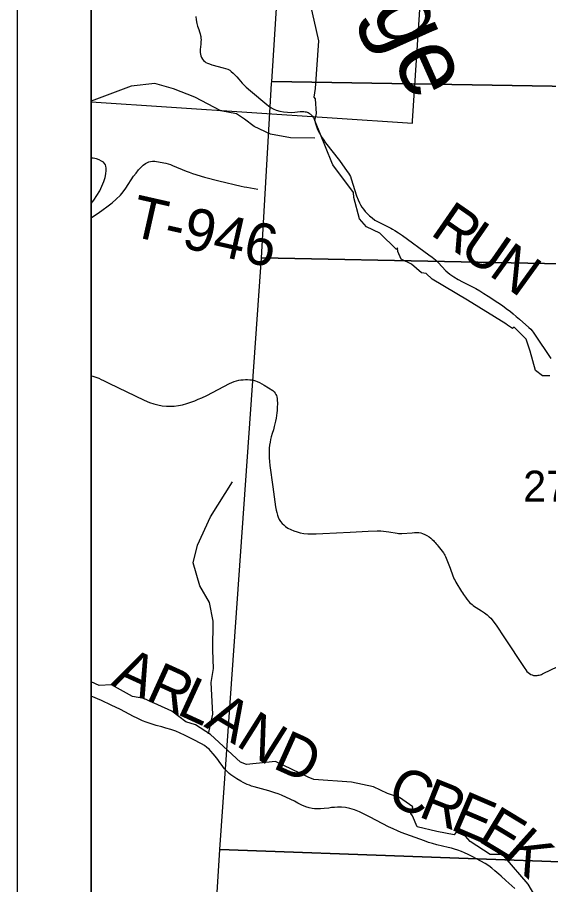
# Model space of a CAD drawing. Extents: x 0 to 34, y 0 to 22.
# Drawn here: x 23.737 to 24.457, y 16.486 to 17.66 of the extents above; entities that cross this region are included whole.
import ezdxf

# ---------------------------------------------------------------- set-up
doc = ezdxf.new("R2010")
doc.units = 0
for name, color, linetype in [('GM_X_County_Road', 7, 'Continuous'), ('GM_X_County_Road_Text', 7, 'Continuous'), ('GM_X_County_Text', 7, 'Continuous'), ('GM_X_Minor_River', 7, 'Continuous'), ('GM_X_Minor_River_Text', 7, 'Continuous'), ('GM_X_Section', 7, 'Continuous'), ('GM_X_Section_Text', 7, 'Continuous'), ('GM_X_State_Shield', 7, 'Continuous'), ('GM_X_Township_Road', 7, 'Continuous'), ('GM_X_Township_Road_Text', 7, 'Continuous'), ('SH_Cut_Line', 7, 'Continuous'), ('SH_Data', 7, 'Continuous')]:
    doc.layers.add(name, color=color, linetype=linetype)

msp = doc.modelspace()

# ---------------------------------------------------------------- linework, layer by layer
at = {"layer": 'GM_X_County_Road'}
for points in [[(23.9787, 17.661), (23.9793, 17.6567), (23.9804, 17.6517), (23.9814, 17.6479), (23.9828, 17.6434), (23.9839, 17.6401), (23.9848, 17.6374), (23.9854, 17.6355), (23.9858, 17.6338), (23.9859, 17.6318), (23.986, 17.6296), (23.9859, 17.627), (23.9857, 17.6242), (23.9852, 17.6197), (23.985, 17.617), (23.985, 17.6143), (23.985, 17.6122), (23.9852, 17.61), (23.9859, 17.6077), (23.9868, 17.6054), (23.988, 17.6033), (23.9894, 17.6015), (23.991, 17.5999), (23.9926, 17.5988), (23.9949, 17.5977), (23.9975, 17.5967), (24.0005, 17.5957), (24.016, 17.5916), (24.0192, 17.5907), (24.0223, 17.5896), (24.0248, 17.5882), (24.027, 17.5867), (24.0295, 17.5845), (24.0322, 17.5817), (24.0346, 17.5791), (24.0372, 17.576), (24.0415, 17.5709), (24.0443, 17.5681), (24.0472, 17.5655), (24.0531, 17.5603), (24.0752, 17.5418), (24.0798, 17.5384), (24.0838, 17.536), (24.0878, 17.5344), (24.0926, 17.5329), (24.0978, 17.5318), (24.1031, 17.5313), (24.1081, 17.5312), (24.1129, 17.5316), (24.1168, 17.5319), (24.12, 17.5322), (24.1222, 17.5323), (24.1237, 17.5323), (24.1254, 17.5323), (24.1268, 17.5321), (24.1284, 17.5318), (24.1297, 17.5314), (24.1311, 17.5308), (24.1323, 17.5302), (24.1334, 17.5294), (24.1344, 17.5287), (24.1353, 17.5278), (24.1362, 17.5269), (24.1369, 17.5261), (24.1382, 17.5243), (24.1388, 17.5232), (24.1393, 17.5221), (24.1401, 17.5199), (24.1407, 17.5174), (24.1413, 17.5149), (24.1422, 17.5121), (24.1433, 17.5092), (24.1446, 17.5062), (24.1462, 17.5031), (24.148, 17.4999), (24.1501, 17.4967), (24.1523, 17.4935), (24.1547, 17.4901), (24.1733, 17.466), (24.1839, 17.4512), (24.1856, 17.4489), (24.1871, 17.4466), (24.1882, 17.4443), (24.1895, 17.4412), (24.1967, 17.4183), (24.1989, 17.4126), (24.2007, 17.4086), (24.2021, 17.4059), (24.2039, 17.4029), (24.2059, 17.4001), (24.2084, 17.3968), (24.211, 17.3941), (24.2143, 17.391), (24.2176, 17.3883), (24.2215, 17.3854), (24.2259, 17.3829), (24.2375, 17.3771), (24.2428, 17.3745), (24.2454, 17.3731), (24.2483, 17.3713), (24.2536, 17.3679), (24.2587, 17.3645), (24.2943, 17.3385), (24.2989, 17.3352), (24.3034, 17.3315), (24.307, 17.3279), (24.3177, 17.3166), (24.3231, 17.3121), (24.3283, 17.3085), (24.3341, 17.305), (24.3402, 17.3017), (24.3472, 17.2981), (24.3526, 17.2955), (24.3582, 17.2927), (24.3636, 17.2896), (24.3691, 17.2861), (24.3749, 17.2823), (24.3877, 17.2738), (24.3941, 17.2695), (24.3994, 17.2655), (24.405, 17.2614), (24.4088, 17.2583), (24.4126, 17.255), (24.4171, 17.2511), (24.4301, 17.2398), (24.4325, 17.2376), (24.4342, 17.2356), (24.4358, 17.2334), (24.4374, 17.2311), (24.4597, 17.1981)], [(23.8372, 17.4077), (23.8408, 17.4125), (23.845, 17.4187), (23.8488, 17.4251), (23.8518, 17.4314), (23.8544, 17.4376), (23.8561, 17.4431), (23.8571, 17.4482), (23.8575, 17.4527), (23.8575, 17.4556), (23.8571, 17.4582), (23.8565, 17.4602), (23.8554, 17.4621), (23.8537, 17.4638), (23.8513, 17.4653), (23.848, 17.4668), (23.8443, 17.4681), (23.8397, 17.4692), (23.8372, 17.4694)], [(23.8372, 17.1747), (23.8394, 17.1741), (23.8422, 17.1733), (23.845, 17.1723), (23.8477, 17.1712), (23.8509, 17.1697), (23.8539, 17.1681), (23.8573, 17.1664), (23.8613, 17.1644), (23.909, 17.1415), (23.916, 17.1386), (23.9219, 17.1365), (23.9275, 17.135), (23.9334, 17.134), (23.9394, 17.1335), (23.9449, 17.1333), (23.9498, 17.1335), (23.9554, 17.1342), (23.961, 17.1354), (23.9668, 17.137), (23.9723, 17.1388), (23.9775, 17.1408), (23.982, 17.1427), (23.987, 17.1448), (23.9937, 17.148), (24.0245, 17.1642), (24.0277, 17.1656), (24.031, 17.1668), (24.034, 17.1677), (24.0371, 17.1684), (24.04, 17.1689), (24.0429, 17.1692), (24.0461, 17.1693), (24.049, 17.1693), (24.0519, 17.1692), (24.0544, 17.1689), (24.057, 17.1685), (24.0596, 17.1677), (24.0622, 17.1667), (24.065, 17.1654), (24.0715, 17.1619), (24.0775, 17.1584), (24.0794, 17.1571), (24.0811, 17.156), (24.0831, 17.1544), (24.0848, 17.1528), (24.0863, 17.151), (24.0874, 17.1492), (24.0882, 17.1477), (24.0887, 17.1461), (24.089, 17.144), (24.0892, 17.1412), (24.0893, 17.1381), (24.0891, 17.1308), (24.0889, 17.1275), (24.0886, 17.1242), (24.0881, 17.1207), (24.0876, 17.1171), (24.0868, 17.1132), (24.0861, 17.1097), (24.0852, 17.106), (24.084, 17.1013), (24.0825, 17.0964), (24.0811, 17.0918), (24.0801, 17.0883), (24.0794, 17.0847), (24.0788, 17.0808), (24.0783, 17.0766), (24.0781, 17.0722), (24.0782, 17.0679), (24.0784, 17.0635), (24.0787, 17.0586), (24.0793, 17.053), (24.0833, 17.0242), (24.087, 16.9971), (24.0877, 16.9926), (24.0884, 16.9893), (24.0893, 16.986), (24.0904, 16.983), (24.0919, 16.9799), (24.0938, 16.9771), (24.0959, 16.9744), (24.0979, 16.9726), (24.1005, 16.9705), (24.1037, 16.9684), (24.1074, 16.9664), (24.1115, 16.9647), (24.1161, 16.9631), (24.1203, 16.9621), (24.1254, 16.9612), (24.1306, 16.9606), (24.1362, 16.9604), (24.142, 16.9604), (24.1508, 16.9608), (24.1879, 16.9629), (24.2124, 16.9642), (24.2247, 16.9647), (24.227, 16.9647), (24.2293, 16.9645), (24.2404, 16.9631), (24.2515, 16.9614), (24.2535, 16.9612), (24.2555, 16.9611), (24.2579, 16.9612), (24.2718, 16.962), (24.2752, 16.9623), (24.2784, 16.9624), (24.2808, 16.9622), (24.2835, 16.9617), (24.2861, 16.9609), (24.289, 16.9597), (24.2919, 16.9583), (24.2948, 16.9565), (24.2973, 16.9546), (24.2991, 16.953), (24.3006, 16.9516), (24.3019, 16.9502), (24.3032, 16.9487), (24.3046, 16.9471), (24.3058, 16.9457), (24.3072, 16.944), (24.3143, 16.9347), (24.3153, 16.9332), (24.3163, 16.9315), (24.3172, 16.9298), (24.3181, 16.9278), (24.3232, 16.9142), (24.327, 16.9039), (24.3279, 16.9016), (24.3289, 16.8994), (24.33, 16.8972), (24.3311, 16.8952), (24.3385, 16.8827), (24.3399, 16.8806), (24.3414, 16.8782), (24.3439, 16.8747), (24.3459, 16.8721), (24.3481, 16.8694), (24.3497, 16.8678), (24.3513, 16.8662), (24.353, 16.8649), (24.3546, 16.8637), (24.3564, 16.8623), (24.3586, 16.8608), (24.362, 16.8586), (24.366, 16.8562), (24.3697, 16.8537), (24.3733, 16.8509), (24.3762, 16.8484), (24.3784, 16.8462), (24.3802, 16.8441), (24.3825, 16.8411), (24.3843, 16.8386), (24.3864, 16.8354), (24.396, 16.8209), (24.4245, 16.7781), (24.4259, 16.7762), (24.4274, 16.7743), (24.4289, 16.7727), (24.4307, 16.7713), (24.4325, 16.7702), (24.4342, 16.7695), (24.4361, 16.7689), (24.438, 16.7687), (24.4396, 16.7687), (24.4412, 16.7688), (24.4426, 16.769), (24.4438, 16.7693), (24.4455, 16.7698), (24.447, 16.7703), (24.4483, 16.7708), (24.4495, 16.7713), (24.469, 16.7811)], [(24.4108, 16.4804), (24.3988, 16.4914), (24.3923, 16.4972), (24.3892, 16.4999), (24.3838, 16.5045), (24.3799, 16.5077), (24.3757, 16.5109), (24.3707, 16.514), (24.3649, 16.5173), (24.3588, 16.5207), (24.3532, 16.5238), (24.3479, 16.5265), (24.3427, 16.5288), (24.3385, 16.5305), (24.3339, 16.5322), (24.3294, 16.5337), (24.325, 16.5349), (24.3205, 16.536), (24.3052, 16.5395), (24.2995, 16.5411), (24.2942, 16.5428), (24.2888, 16.5447), (24.2569, 16.5563), (24.252, 16.5583), (24.2461, 16.561), (24.2397, 16.564), (24.2152, 16.5769), (24.2069, 16.5812), (24.2006, 16.584), (24.1936, 16.5868), (24.1873, 16.5886), (24.1814, 16.5898), (24.176, 16.5903), (24.1709, 16.5904), (24.1669, 16.5902), (24.1626, 16.5898), (24.1589, 16.5893), (24.1527, 16.5885), (24.1479, 16.5881), (24.1436, 16.588), (24.1397, 16.5881), (24.1364, 16.5886), (24.1323, 16.5894), (24.1277, 16.5909), (24.1226, 16.5931), (24.117, 16.5961), (24.1127, 16.5984), (24.1078, 16.6007), (24.095, 16.6067), (24.0904, 16.6085), (24.086, 16.6101), (24.0819, 16.6113), (24.0776, 16.6124), (24.0579, 16.618), (24.0545, 16.619), (24.0515, 16.6201), (24.0486, 16.6212), (24.0458, 16.6225), (24.0429, 16.6239), (24.0398, 16.6256), (24.0345, 16.6287), (24.0289, 16.6325), (24.0262, 16.6343), (24.024, 16.6361), (24.0218, 16.6381), (24.02, 16.6401), (24.0179, 16.6425), (24.0164, 16.6443), (24.0144, 16.6468), (24.0127, 16.6492), (24.0074, 16.6566), (24.0025, 16.6629), (23.9993, 16.6664), (23.997, 16.6688), (23.994, 16.6713), (23.9906, 16.6738), (23.9865, 16.6764), (23.9832, 16.6782), (23.979, 16.6803), (23.9634, 16.6881), (23.9577, 16.6908), (23.9517, 16.6933), (23.9452, 16.6955), (23.9384, 16.6975), (23.9327, 16.6991), (23.9251, 16.7011), (23.9184, 16.7031), (23.9118, 16.7054), (23.9068, 16.7074), (23.9031, 16.7091), (23.8994, 16.7109), (23.8946, 16.7133), (23.877, 16.7225), (23.8641, 16.7288), (23.8512, 16.7349), (23.8372, 16.7406)]]:
    msp.add_lwpolyline(points, dxfattribs=at)
at = {"layer": 'GM_X_County_Text'}
msp.add_lwpolyline([(23.8372, 20.6485), (23.8372, 14.4177), (24.4263, 14.3937), (25.7269, 14.3414), (26.0929, 14.3266), (26.1939, 14.3226), (26.568, 14.3076), (26.7502, 14.2997), (27.0716, 14.2873), (27.1862, 14.3829)], dxfattribs=at)
at = {"layer": 'GM_X_Minor_River'}
for points in [[(24.4584, 17.1743), (24.4485, 17.1743), (24.4387, 17.1818), (24.4319, 17.2077), (24.4262, 17.224), (24.4099, 17.2403), (24.4076, 17.2384), (24.4012, 17.2429), (24.3986, 17.2448), (24.3468, 17.277), (24.2991, 17.3054), (24.2908, 17.313), (24.2847, 17.3141), (24.2711, 17.3255), (24.2571, 17.3323), (24.2526, 17.3426), (24.2522, 17.3479), (24.2507, 17.3456), (24.2283, 17.3676), (24.2102, 17.3763), (24.2004, 17.3869), (24.1928, 17.4158), (24.1924, 17.4226), (24.1644, 17.4602), (24.1632, 17.4632), (24.1401, 17.5202), (24.1424, 17.5297), (24.1412, 17.5494), (24.139, 17.5517), (24.1408, 17.5635), (24.1453, 17.6281), (24.1336, 17.6801)], [(24.1401, 17.4964), (24.1072, 17.4967), (24.0802, 17.5017), (24.0578, 17.5119), (24.0449, 17.5218), (24.0341, 17.5294), (24.0127, 17.5331), (23.9774, 17.5517), (23.9486, 17.5629), (23.9235, 17.5701), (23.8913, 17.5666), (23.8372, 17.5464)], [(23.9959, 16.6896), (24.002, 16.7164), (23.9999, 16.7594), (24.0028, 16.7782), (24.002, 16.803), (24.0025, 16.8424), (23.9976, 16.8676), (23.9843, 16.8901), (23.9754, 16.9211), (23.981, 16.9452), (23.9988, 16.9838), (24.0286, 17.031)], [(23.9653, 16.7061), (23.9462, 16.7205), (23.9087, 16.7375), (23.8932, 16.7405), (23.8645, 16.756), (23.8482, 16.7552), (23.8372, 16.7601)], [(24.456, 16.4404), (24.4288, 16.4864), (24.3977, 16.5224), (24.3951, 16.5262), (24.3777, 16.5265), (24.3504, 16.5439), (24.344, 16.5511), (24.3315, 16.5568), (24.3289, 16.553), (24.3051, 16.5575), (24.2786, 16.5639), (24.2725, 16.5787), (24.2699, 16.5821), (24.2729, 16.5909), (24.2548, 16.6034), (24.2411, 16.6083), (24.2385, 16.609), (24.2196, 16.6181), (24.1897, 16.6241), (24.1387, 16.6278), (24.1311, 16.6312), (24.0869, 16.6524), (24.0476, 16.6481), (24.0392, 16.6515), (23.9988, 16.6887), (23.9783, 16.7019), (23.9653, 16.7061)]]:
    msp.add_lwpolyline(points, dxfattribs=at)
at = {"layer": 'GM_X_Section'}
for points in [[(24.0951, 17.7788), (25.1245, 17.7506), (25.1122, 17.5559), (24.0818, 17.5731)], [(24.0815, 17.5702), (24.0818, 17.5731), (25.1122, 17.5559), (25.097, 17.3132), (24.6087, 17.3232), (24.0677, 17.3343)], [(24.6087, 17.3232), (24.5596, 16.5135), (24.0115, 16.5331), (24.0677, 17.3343)], [(24.5596, 16.5135), (25.0459, 16.4982), (25.0486, 16.498), (25.0369, 16.3074), (25.0112, 15.8778), (24.9883, 15.4512), (23.9474, 15.5054), (24.0115, 16.5331)]]:
    msp.add_lwpolyline(points, close=True, dxfattribs=at)
at = {"layer": 'GM_X_State_Shield'}
msp.add_lwpolyline([(23.8372, 18.5819), (23.8372, 17.5453), (24.2723, 17.5167), (24.2725, 17.5197), (24.2859, 17.7254), (24.3093, 18.1388), (24.3364, 18.5641)], close=True, dxfattribs=at)
at = {"layer": 'GM_X_Township_Road'}
msp.add_lwpolyline([(23.8372, 17.3886), (23.8376, 17.3889), (23.8466, 17.3948), (23.8534, 17.3995), (23.8585, 17.4032), (23.8655, 17.4086), (23.8712, 17.4136), (23.8769, 17.4193), (23.8806, 17.4235), (23.8843, 17.4284), (23.8947, 17.4446), (23.8979, 17.4491), (23.9013, 17.4532), (23.9045, 17.4565), (23.9078, 17.4595), (23.9109, 17.4618), (23.9133, 17.4632), (23.9154, 17.4643), (23.9175, 17.4649), (23.9201, 17.4652), (23.9217, 17.4652), (23.9233, 17.465), (23.9357, 17.463), (23.9385, 17.4625), (23.9415, 17.4616), (23.9445, 17.4606), (23.9475, 17.4594), (23.9659, 17.4518), (23.9699, 17.4503), (23.9746, 17.4486), (23.9905, 17.4436), (24.0102, 17.4385), (24.0401, 17.4314), (24.0442, 17.4306), (24.0481, 17.4298), (24.0631, 17.4273)], dxfattribs=at)
at = {"layer": 'SH_Cut_Line'}
msp.add_lwpolyline([(23.8372, 20.9), (23.8372, 14.4177), (24.4263, 14.3937), (25.7269, 14.3414), (26.0929, 14.3266), (26.1939, 14.3226), (26.568, 14.3076), (26.7502, 14.2997), (27.0716, 14.2873), (27.1862, 14.3829)], dxfattribs=at)
at = {"layer": 'SH_Data'}
for points in [[(23.7372, 21), (30.7372, 21), (30.7372, 14), (23.7372, 14)], [(23.8372, 20.9), (30.6372, 20.9), (30.6372, 14.1), (23.8372, 14.1)]]:
    msp.add_lwpolyline(points, close=True, dxfattribs=at)

# ---------------------------------------------------------------- texts
at = {"layer": 'GM_X_County_Road_Text'}
for s, rotation, p in [('R', 325.307, (24.2949, 17.3666)), ('U', 325.2799, (24.3332, 17.3401)), ('N', 324.1181, (24.3741, 17.3118)), ('A', 335.5739, (23.8635, 16.7571)), ('R', 335.5675, (23.909, 16.7365)), ('L', 335.3596, (23.9514, 16.7172)), ('A', 329.358, (23.9887, 16.7002)), ('N', 327.7907, (24.0314, 16.6749)), ('D', 335.775, (24.0813, 16.6442)), ('C', 338.2729, (24.2354, 16.5957)), ('R', 338.2283, (24.2787, 16.5784)), ('E', 336.8889, (24.3218, 16.5612)), ('E', 328.8205, (24.359, 16.5455)), ('K', 318.0358, (24.3931, 16.5252))]:
    msp.add_text(s, height=0.0568, rotation=rotation, dxfattribs=at).set_placement(p)
at = {"layer": 'GM_X_Minor_River_Text'}
msp.add_text('George', height=0.09469, rotation=294.1351, dxfattribs=at).set_placement((24.1001, 17.928))
at = {"layer": 'GM_X_Section_Text'}
msp.add_text('27', height=0.04186, rotation=0, dxfattribs=at).set_placement((24.4222, 17.0042))
at = {"layer": 'GM_X_Township_Road_Text'}
msp.add_text('T-946', height=0.05682, rotation=347.238, dxfattribs=at).set_placement((23.888, 17.3645))

doc.saveas('drawing.dxf')
